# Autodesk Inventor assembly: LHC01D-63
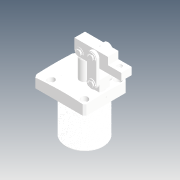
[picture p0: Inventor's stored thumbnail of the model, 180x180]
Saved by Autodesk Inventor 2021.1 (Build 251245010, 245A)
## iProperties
Created: 2019-04
Part Number: LHC01D-63
Description: STEP AP214
Document SubType Name: Assembly
Designer: user
Title: LHC01D-63.STEP
Revision Number: ÈÎºÎ
Sending System: SolidWorks 2016
Preprocessor: SwSTEP 2.0
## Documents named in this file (12)
- D:\Vault_2016\Projekty\Clamptek\Hydraulic\LHC01D\Inventor\LHC01D-63\LHC01D-63.iam
- D:\Vault_2016\Projekty\Clamptek\Hydraulic\LHC01D\Inventor\LHC01D-63\LHC01D-63-01.ipt
- D:\Vault_2016\Projekty\Clamptek\Hydraulic\LHC01D\Inventor\LHC01D-63\CPLCU-63-01.ipt
- D:\Vault_2016\Projekty\Clamptek\Hydraulic\LHC01D\Inventor\LHC01D-63\CPLCU-63-05.ipt
- D:\Vault_2016\Projekty\Clamptek\Hydraulic\LHC01D\Inventor\LHC01D-63\CPLCU-63-03.ipt
- D:\Vault_2016\Projekty\Clamptek\Hydraulic\LHC01D\Inventor\LHC01D-63\CPLCU-63-02.ipt
- D:\Vault_2016\Projekty\Clamptek\Hydraulic\LHC01D\Inventor\LHC01D-63\LHC01D-63-07.ipt
- D:\Vault_2016\Projekty\Clamptek\Hydraulic\LHC01D\Inventor\LHC01D-63\CPLCU-63-04.ipt
- D:\Vault_2016\Projekty\Clamptek\Hydraulic\LHC01D\Inventor\LHC01D-63\CPLCU-50-08_3.ipt
- D:\Vault_2016\Projekty\Clamptek\Hydraulic\LHC01D\Inventor\LHC01D-63\M4ningjin_8.ipt
- D:\Vault_2016\Projekty\Clamptek\Hydraulic\LHC01D\Inventor\LHC01D-63\¶ÂÍ·_13.ipt
- D:\Vault_2016\Projekty\Clamptek\Hydraulic\LHC01D\Inventor\LHC01D-63\LHC01D63±¾Ìå.ipt
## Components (25 placed, 25 different names)
1. LHC01D-63-01_1
2. CPLCU-63-01_2
3. CPLCU-63-05_3
4. CPLCU-63-03_4
5. CPLCU-63-02_5
6. CPLCU-63-02_6
7. LHC01D-63-07_7
8. LHC01D-63-07_8
9. LHC01D-63-07_9
10. LHC01D-63-07_10
11. LHC01D-63-07_11
12. LHC01D-63-07_12
13. CPLCU-63-04_13
14. CPLCU-63-04_14
15. CPLCU-50-08_3_15
16. CPLCU-50-08_3_16
17. CPLCU-50-08_3_17
18. CPLCU-50-08_3_18
19. CPLCU-50-08_3_19
20. CPLCU-50-08_3_20
21. M4ningjin_8_21
22. ¶ÂÍ·_13_22
23. ¶ÂÍ·_13_23
24. M4ningjin_8_24
25. LHC01D63±¾Ìå_25
